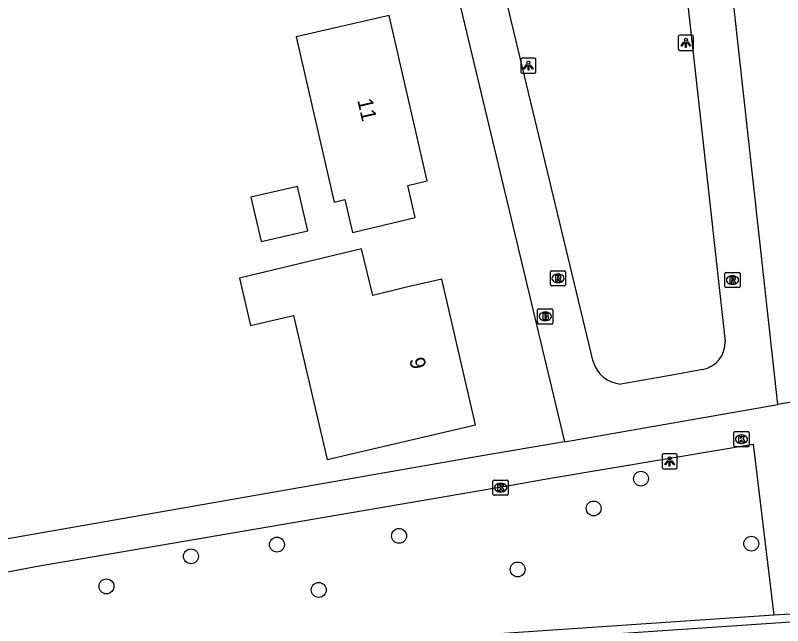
# Model space of a CAD drawing. Extents: x 162675 to 163482, y 379761 to 381227.
# Drawn here: x 162956.8 to 163007.2, y 380352.7 to 380392.8 of the extents above; entities that cross this region are included whole.
import ezdxf

# ---------------------------------------------------------------- set-up
doc = ezdxf.new("R2010")
doc.units = 0
for name, color, linetype in [('IMGEO_Boom', 7, 'Continuous'), ('IMGEO_Brandkraan', 7, 'Continuous'), ('IMGEO_Kolk', 7, 'Continuous'), ('IMGEO_Lichtpunt', 7, 'Continuous'), ('IMGEO_Pand', 7, 'Continuous'), ('IMGEO_Pand_nummerreeks', 7, 'Continuous'), ('IMGEO_Rijbaan_lokaal_gesloten', 7, 'Continuous'), ('IMGEO_Rijbaan_lokaal_open', 7, 'Continuous'), ('IMGEO_Rioolput', 7, 'Continuous'), ('IMGEO_Voetpad_open', 7, 'Continuous')]:
    doc.layers.add(name, color=color, linetype=linetype)

msp = doc.modelspace()

# ---------------------------------------------------------------- linework, layer by layer
at = {"layer": 'IMGEO_Boom'}
for centre in [(162997.848, 380362.374), (162994.736, 380360.416), (162981.956, 380358.616), (162973.936, 380358.043), (163005.09, 380358.105), (162968.286, 380357.27), (162989.744, 380356.409), (162962.74, 380355.298), (162976.682, 380355.067)]:
    msp.add_circle(centre, 0.489, dxfattribs=at)
at = {"layer": 'IMGEO_Brandkraan'}
for p, q in [((162991.134, 380373.528), (162991.986, 380373.528)), ((162991.059, 380372.602), (162991.059, 380373.454)), ((162991.547, 380373.308), (162991.572, 380373.308)), ((162992.06, 380373.454), (162992.06, 380372.602)), ((162991.986, 380372.528), (162991.134, 380372.528)), ((162991.57, 380372.748), (162991.545, 380372.748))]:
    msp.add_line(p, q, dxfattribs=at)
for points in [[(162991.134, 380373.528), (162991.986, 380373.528)], [(162991.059, 380372.602), (162991.059, 380373.454)], [(162991.407, 380373.228), (162991.407, 380372.828), (162991.62, 380372.828)], [(162991.638, 380373.228), (162991.407, 380373.228)], [(162991.586, 380373.147), (162991.532, 380373.147), (162991.532, 380373.071)], [(162991.532, 380373.071), (162991.585, 380373.071)], [(162991.594, 380372.995), (162991.532, 380372.995), (162991.532, 380372.914)], [(162992.06, 380373.454), (162992.06, 380372.602)], [(162991.986, 380372.528), (162991.134, 380372.528)], [(162991.532, 380372.914), (162991.594, 380372.914)]]:
    msp.add_lwpolyline(points, dxfattribs=at)
for centre, radius, start, end in [((162991.136, 380373.452), 0.0765, 91.552, 178.448), ((162991.136, 380373.452), 0.0765, 91.552, 178.448), ((162991.984, 380373.452), 0.0765, 1.552, 88.448), ((162991.984, 380373.452), 0.0765, 1.552, 88.448), ((162991.587, 380373.109), 0.0379, 267.8285, 90.9355), ((162991.595, 380372.954), 0.0404, 269.8759, 90.5077), ((162991.642, 380373.083), 0.145, 59.4692, 91.5367), ((162991.667, 380373.13), 0.0922, 285.5137, 58.1501), ((162991.672, 380372.938), 0.105, 301.3115, 78.989), ((162991.136, 380372.604), 0.0765, 181.552, 268.448), ((162991.136, 380372.604), 0.0765, 181.552, 268.448), ((162991.626, 380373.079), 0.251, 268.6676, 293.5347), ((162991.984, 380372.604), 0.0765, 271.552, 358.448), ((162991.984, 380372.604), 0.0765, 271.552, 358.448)]:
    msp.add_arc(centre, radius, start, end, dxfattribs=at)
for centre, major_axis, ratio, start_param, end_param in [((162991.546, 380373.028), (-0.387, 0.002), 0.722429, 4.712389, 7.853982), ((162991.571, 380373.028), (-0.39, 0.002), 0.717154, 1.570796, 4.712389)]:
    msp.add_ellipse(centre, major_axis=major_axis, ratio=ratio, start_param=start_param, end_param=end_param, dxfattribs=at)
at = {"layer": 'IMGEO_Kolk'}
for p, q in [((163004.019, 380365.463), (163004.871, 380365.463)), ((163003.944, 380364.537), (163003.944, 380365.389)), ((163004.432, 380365.243), (163004.457, 380365.243)), ((163004.945, 380365.389), (163004.945, 380364.537)), ((163004.871, 380364.463), (163004.019, 380364.463)), ((163004.455, 380364.683), (163004.43, 380364.683)), ((162988.125, 380361.355), (162988.125, 380362.207)), ((162988.2, 380362.281), (162989.052, 380362.281)), ((162988.613, 380362.061), (162988.638, 380362.061)), ((162989.126, 380362.207), (162989.126, 380361.355)), ((162988.636, 380361.501), (162988.611, 380361.501)), ((162989.052, 380361.281), (162988.2, 380361.281))]:
    msp.add_line(p, q, dxfattribs=at)
for points in [[(163004.019, 380365.463), (163004.871, 380365.463)], [(163003.944, 380364.537), (163003.944, 380365.389)], [(163004.265, 380365.163), (163004.388, 380365.163), (163004.388, 380365.012), (163004.518, 380365.163), (163004.682, 380365.163), (163004.536, 380365.012), (163004.689, 380364.763), (163004.537, 380364.763), (163004.452, 380364.927), (163004.388, 380364.86), (163004.388, 380364.763), (163004.265, 380364.763), (163004.265, 380365.163)], [(163004.945, 380365.389), (163004.945, 380364.537)], [(163004.871, 380364.463), (163004.019, 380364.463)], [(162988.125, 380361.355), (162988.125, 380362.207)], [(162988.2, 380362.281), (162989.052, 380362.281)], [(162988.446, 380361.981), (162988.569, 380361.981), (162988.569, 380361.83), (162988.699, 380361.981), (162988.863, 380361.981), (162988.717, 380361.83), (162988.87, 380361.581), (162988.718, 380361.581), (162988.633, 380361.745), (162988.569, 380361.678), (162988.569, 380361.581), (162988.446, 380361.581), (162988.446, 380361.981)], [(162989.126, 380362.207), (162989.126, 380361.355)], [(162989.052, 380361.281), (162988.2, 380361.281)]]:
    msp.add_lwpolyline(points, dxfattribs=at)
for centre, start, end in [((163004.021, 380365.387), 91.552, 178.448), ((163004.021, 380365.387), 91.552, 178.448), ((163004.869, 380365.387), 1.552, 88.448), ((163004.869, 380365.387), 1.552, 88.448), ((163004.021, 380364.539), 181.552, 268.448), ((163004.021, 380364.539), 181.552, 268.448), ((163004.869, 380364.539), 271.552, 358.448), ((163004.869, 380364.539), 271.552, 358.448), ((162988.202, 380362.205), 91.552, 178.448), ((162988.202, 380362.205), 91.552, 178.448), ((162989.05, 380362.205), 1.552, 88.448), ((162989.05, 380362.205), 1.552, 88.448), ((162988.202, 380361.357), 181.552, 268.448), ((162988.202, 380361.357), 181.552, 268.448), ((162989.05, 380361.357), 271.552, 358.448), ((162989.05, 380361.357), 271.552, 358.448)]:
    msp.add_arc(centre, 0.0765, start, end, dxfattribs=at)
for centre, major_axis, ratio, start_param, end_param in [((163004.431, 380364.963), (-0.387, 0.002), 0.722429, 4.712389, 7.853982), ((163004.456, 380364.963), (-0.39, 0.002), 0.717154, 1.570796, 4.712389), ((162988.612, 380361.781), (-0.387, 0.002), 0.722429, 4.712389, 7.853982), ((162988.637, 380361.781), (-0.39, 0.002), 0.717154, 1.570796, 4.712389)]:
    msp.add_ellipse(centre, major_axis=major_axis, ratio=ratio, start_param=start_param, end_param=end_param, dxfattribs=at)
at = {"layer": 'IMGEO_Lichtpunt'}
for p, q in [((163000.297, 380391.396), (163000.297, 380390.589)), ((163000.297, 380391.396), (163000.297, 380390.589)), ((163001.199, 380391.491), (163000.391, 380391.491)), ((163001.199, 380391.491), (163000.391, 380391.491)), ((163001.293, 380390.589), (163001.293, 380391.396)), ((163001.293, 380390.589), (163001.293, 380391.396)), ((163000.391, 380390.495), (163001.199, 380390.495)), ((163000.391, 380390.495), (163001.199, 380390.495)), ((162989.95, 380389.894), (162989.95, 380389.087)), ((162989.95, 380389.894), (162989.95, 380389.087)), ((162990.852, 380389.989), (162990.044, 380389.989)), ((162990.852, 380389.989), (162990.044, 380389.989)), ((162990.946, 380389.087), (162990.946, 380389.894)), ((162990.946, 380389.087), (162990.946, 380389.894)), ((162990.044, 380388.993), (162990.852, 380388.993)), ((162990.044, 380388.993), (162990.852, 380388.993)), ((163000.13, 380364.004), (162999.322, 380364.004)), ((163000.13, 380364.004), (162999.322, 380364.004)), ((162999.228, 380363.909), (162999.228, 380363.102)), ((162999.228, 380363.909), (162999.228, 380363.102)), ((163000.224, 380363.102), (163000.224, 380363.909)), ((163000.224, 380363.102), (163000.224, 380363.909)), ((162999.322, 380363.008), (163000.13, 380363.008)), ((162999.322, 380363.008), (163000.13, 380363.008))]:
    msp.add_line(p, q, dxfattribs=at)
for points in [[(163000.671, 380391.06), (163000.71, 380391.032), (163000.522, 380390.77), (163000.484, 380390.797), (163000.671, 380391.06)], [(163000.773, 380391.012), (163000.82, 380391.012), (163000.82, 380390.69), (163000.773, 380390.69), (163000.773, 380391.012)], [(163000.883, 380391.032), (163000.921, 380391.059), (163001.108, 380390.797), (163001.069, 380390.769), (163000.883, 380391.032)], [(162990.324, 380389.558), (162990.363, 380389.53), (162990.175, 380389.268), (162990.137, 380389.295), (162990.324, 380389.558)], [(162990.426, 380389.51), (162990.473, 380389.51), (162990.473, 380389.188), (162990.426, 380389.188), (162990.426, 380389.51)], [(162990.536, 380389.53), (162990.574, 380389.557), (162990.761, 380389.295), (162990.722, 380389.267), (162990.536, 380389.53)], [(162999.602, 380363.573), (162999.641, 380363.545), (162999.453, 380363.283), (162999.415, 380363.31), (162999.602, 380363.573)], [(162999.704, 380363.525), (162999.751, 380363.525), (162999.751, 380363.203), (162999.704, 380363.203), (162999.704, 380363.525)], [(162999.814, 380363.545), (162999.852, 380363.572), (163000.039, 380363.31), (163000, 380363.282), (162999.814, 380363.545)]]:
    msp.add_lwpolyline(points, dxfattribs=at)
for centre in [(163000.796, 380391.194), (162990.449, 380389.692), (162999.727, 380363.707)]:
    msp.add_circle(centre, 0.0994, dxfattribs=at)
for centre, start, end in [((163000.391, 380391.396), 90, 180), ((163000.391, 380391.396), 90, 180), ((163001.199, 380391.396), 0, 90), ((163001.199, 380391.396), 0, 90), ((163000.391, 380390.589), 180, 270), ((163000.391, 380390.589), 180, 270), ((163001.199, 380390.589), 270, 0), ((163001.199, 380390.589), 270, 360), ((162990.044, 380389.894), 90, 180), ((162990.044, 380389.894), 90, 180), ((162990.852, 380389.894), 0, 90), ((162990.852, 380389.894), 0, 90), ((162990.044, 380389.087), 180, 270), ((162990.044, 380389.087), 180, 270), ((162990.852, 380389.087), 270, 0), ((162990.852, 380389.087), 270, 360), ((162999.322, 380363.909), 90, 180), ((162999.322, 380363.909), 90, 180), ((163000.13, 380363.909), 0, 90), ((163000.13, 380363.909), 0, 90), ((162999.322, 380363.102), 180, 270), ((162999.322, 380363.102), 180, 270), ((163000.13, 380363.102), 270, 0), ((163000.13, 380363.102), 270, 360)]:
    msp.add_arc(centre, 0.0946, start, end, dxfattribs=at)
at = {"layer": 'IMGEO_Pand'}
for points in [[(162978.9, 380378.536), (162983.018, 380379.52), (162982.534, 380381.629), (162983.793, 380381.919), (162981.296, 380392.79), (162975.198, 380391.388), (162977.693, 380380.534), (162978.403, 380380.697), (162978.9, 380378.536)], [(162972.219, 380380.862), (162972.889, 380377.95), (162975.954, 380378.655), (162975.285, 380381.566), (162972.219, 380380.862)], [(162982.452, 380374.94), (162980.227, 380374.409), (162979.492, 380377.472), (162971.47, 380375.545), (162972.2, 380372.426), (162975.026, 380373.087), (162977.24, 380363.634), (162986.986, 380365.917), (162984.767, 380375.463), (162982.452, 380374.94)]]:
    msp.add_lwpolyline(points, dxfattribs=at)
at = {"layer": 'IMGEO_Rijbaan_lokaal_gesloten'}
msp.add_lwpolyline([(162940.821, 380348.438), (163054.493, 380356.141)], dxfattribs=at)
at = {"layer": 'IMGEO_Rijbaan_lokaal_open'}
for points in [[(163006.844, 380367.252), (163000.715, 380422.638)], [(162997.616, 380422.36), (162997.93, 380419.975), (163000, 380401.781), (163003.383, 380371.369)], [(162994.695, 380370.063), (162983.47, 380416.805), (162982.667, 380419.816)], [(162979.749, 380419.019), (162980.426, 380416.595), (162992.818, 380364.786)], [(163001.901, 380369.535), (163000, 380369.199), (162996.513, 380368.584)], [(162992.818, 380364.786), (163006.844, 380367.252)], [(163006.568, 380353.401), (162940.787, 380348.935)], [(163008.76, 380353.55), (163006.568, 380353.401)]]:
    msp.add_lwpolyline(points, dxfattribs=at)
for centre, radius, start, end in [((163001.524, 380371.355), 1.859, 281.6989, 0.4199), ((162996.683, 380370.65), 2.073, 196.4576, 265.2836)]:
    msp.add_arc(centre, radius, start, end, dxfattribs=at)
at = {"layer": 'IMGEO_Rioolput'}
for p, q in [((162991.971, 380376.024), (162992.823, 380376.024)), ((162991.896, 380375.098), (162991.896, 380375.95)), ((162992.384, 380375.804), (162992.409, 380375.804)), ((162992.897, 380375.95), (162992.897, 380375.098)), ((163003.353, 380374.989), (163003.353, 380375.841)), ((163003.428, 380375.915), (163004.28, 380375.915)), ((163003.841, 380375.695), (163003.866, 380375.695)), ((163004.354, 380375.841), (163004.354, 380374.989)), ((162992.823, 380375.024), (162991.971, 380375.024)), ((162992.407, 380375.244), (162992.382, 380375.244)), ((163003.864, 380375.135), (163003.839, 380375.135)), ((163004.28, 380374.915), (163003.428, 380374.915))]:
    msp.add_line(p, q, dxfattribs=at)
for points in [[(162991.971, 380376.024), (162992.823, 380376.024)], [(162991.896, 380375.098), (162991.896, 380375.95)], [(162992.485, 380375.722), (162992.233, 380375.724), (162992.233, 380375.324)], [(162992.411, 380375.643), (162992.357, 380375.643), (162992.357, 380375.562)], [(162992.357, 380375.562), (162992.409, 380375.562)], [(162992.897, 380375.95), (162992.897, 380375.098)], [(163003.353, 380374.989), (163003.353, 380375.841)], [(163003.428, 380375.915), (163004.28, 380375.915)], [(163003.942, 380375.613), (163003.69, 380375.615), (163003.69, 380375.215)], [(163003.868, 380375.534), (163003.814, 380375.534), (163003.814, 380375.453)], [(163004.354, 380375.841), (163004.354, 380374.989)], [(162992.823, 380375.024), (162991.971, 380375.024)], [(162992.233, 380375.324), (162992.357, 380375.324), (162992.357, 380375.486), (162992.368, 380375.486)], [(162992.415, 380375.457), (162992.486, 380375.324), (162992.626, 380375.324), (162992.561, 380375.45)], [(163003.69, 380375.215), (163003.814, 380375.215), (163003.814, 380375.377), (163003.825, 380375.377)], [(163003.814, 380375.453), (163003.866, 380375.453)], [(163003.872, 380375.348), (163003.943, 380375.215), (163004.083, 380375.215), (163004.018, 380375.341)], [(163004.28, 380374.915), (163003.428, 380374.915)]]:
    msp.add_lwpolyline(points, dxfattribs=at)
for centre, radius, start, end in [((162991.973, 380375.948), 0.0765, 91.552, 178.448), ((162991.973, 380375.948), 0.0765, 91.552, 178.448), ((162992.821, 380375.948), 0.0765, 1.552, 88.448), ((162992.821, 380375.948), 0.0765, 1.552, 88.448), ((162992.393, 380375.751), 0.19, 274.7715, 282.9687), ((162992.417, 380375.547), 0.0964, 77.0061, 93.1865), ((162992.431, 380375.604), 0.0378, 276.6634, 79.6772), ((162992.484, 380375.612), 0.109, 350.3612, 89.416), ((162992.482, 380375.612), 0.112, 277.5842, 350.9817), ((163003.43, 380375.839), 0.0765, 91.552, 178.448), ((163003.43, 380375.839), 0.0765, 91.552, 178.448), ((163003.874, 380375.438), 0.0964, 77.0061, 93.1865), ((163003.888, 380375.495), 0.0378, 276.6634, 79.6772), ((163003.941, 380375.503), 0.109, 350.3612, 89.416), ((163004.278, 380375.839), 0.0765, 1.552, 88.448), ((163004.278, 380375.839), 0.0765, 1.552, 88.448), ((162991.973, 380375.1), 0.0765, 181.552, 268.448), ((162991.973, 380375.1), 0.0765, 181.552, 268.448), ((162992.367, 380375.433), 0.0533, 26.0293, 88.6989), ((162992.466, 380375.397), 0.108, 29.5134, 73.7905), ((162992.821, 380375.1), 0.0765, 271.552, 358.448), ((162992.821, 380375.1), 0.0765, 271.552, 358.448), ((163003.824, 380375.324), 0.0533, 26.0293, 88.6989), ((163003.85, 380375.642), 0.19, 274.7715, 282.9687), ((163003.939, 380375.503), 0.112, 277.5842, 350.9817), ((163003.923, 380375.288), 0.108, 29.5134, 73.7905), ((163003.43, 380374.991), 0.0765, 181.552, 268.448), ((163003.43, 380374.991), 0.0765, 181.552, 268.448), ((163004.278, 380374.991), 0.0765, 271.552, 358.448), ((163004.278, 380374.991), 0.0765, 271.552, 358.448)]:
    msp.add_arc(centre, radius, start, end, dxfattribs=at)
for centre, major_axis, ratio, start_param, end_param in [((162992.383, 380375.524), (-0.387, 0.002), 0.722429, 4.712389, 7.853982), ((162992.408, 380375.524), (-0.39, 0.002), 0.717154, 1.570796, 4.712389), ((163003.84, 380375.415), (-0.387, 0.002), 0.722429, 4.712389, 7.853982), ((163003.865, 380375.415), (-0.39, 0.002), 0.717154, 1.570796, 4.712389)]:
    msp.add_ellipse(centre, major_axis=major_axis, ratio=ratio, start_param=start_param, end_param=end_param, dxfattribs=at)
at = {"layer": 'IMGEO_Voetpad_open'}
for points in [[(163056.95, 380375.873), (163011.947, 380368.147), (163006.844, 380367.252)], [(162937.978, 380353.182), (162950.999, 380355.403), (162953.727, 380355.77), (162958.085, 380356.605), (162973.327, 380359.209), (162989.055, 380361.908), (162991.897, 380362.399), (163000, 380363.76), (163005.21, 380364.635), (163006.568, 380353.401)], [(162992.818, 380364.786), (162987.152, 380363.833), (162952.002, 380357.671)]]:
    msp.add_lwpolyline(points, dxfattribs=at)

# ---------------------------------------------------------------- texts
at = {"layer": 'IMGEO_Pand_nummerreeks'}
for s, rotation, p in [('11', 282.9361, (162979.208, 380387.226)), ('9', 283.0862, (162982.62, 380370.215))]:
    msp.add_text(s, height=1, rotation=rotation, dxfattribs=at).set_placement(p)

doc.saveas('drawing.dxf')
